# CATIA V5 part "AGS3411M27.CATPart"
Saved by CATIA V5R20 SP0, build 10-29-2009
Part number: AGS3411M27
Definition: NONE
Nomenclature: AGS3411M27
Source: Unknown
Description: AGS3411M27
Bounding box of the stored display mesh (mm): x -35 to 33, y -17.347 to 17.347, z -14.958 to 14.958
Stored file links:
  C:\Users\Utente\Desktop\IO LAVORO\3D X SITO CF\X SITO\PLASTICA\AGS\AGS3411M27.CATPart
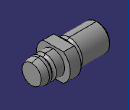
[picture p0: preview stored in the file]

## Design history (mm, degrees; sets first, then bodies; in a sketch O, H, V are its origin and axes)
Body1 "AGS3411M27" (main body)
  Solid1: solid without history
